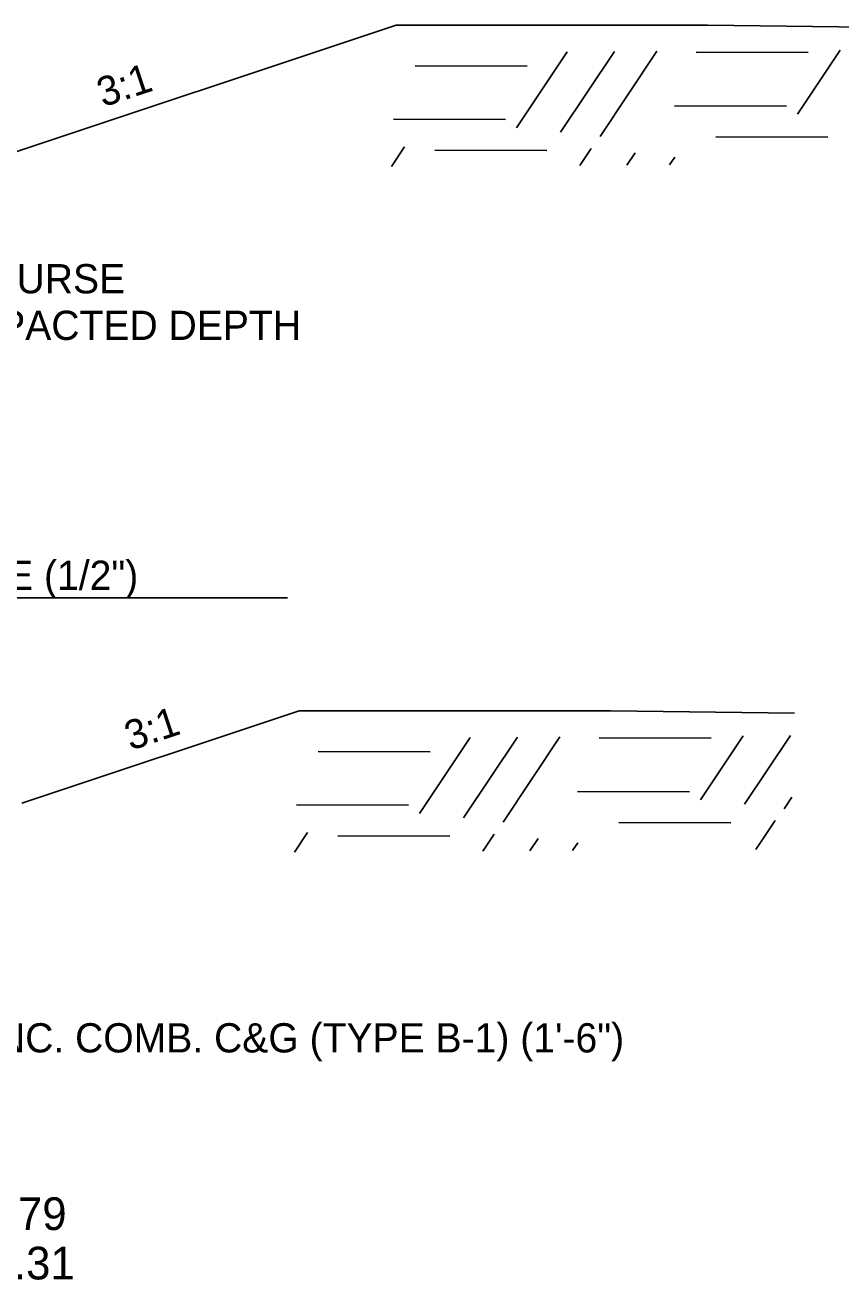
# Model space of a CAD drawing. Extents: x 1398183 to 1398373, y 1967240 to 1968889.
# Drawn here: x 1398289.03 to 1398305.5, y 1968479.92 to 1968505.23 of the extents above; entities that cross this region are included whole.
import ezdxf

# ---------------------------------------------------------------- set-up
doc = ezdxf.new("R2010")
doc.units = 0
for name, color, linetype in [('10', 7, 'Continuous'), ('19', 7, 'Continuous'), ('42', 7, 'Continuous'), ('9', 7, 'Continuous')]:
    doc.layers.add(name, color=color, linetype=linetype)

msp = doc.modelspace()

# ---------------------------------------------------------------- linework, layer by layer
at = {"layer": '19'}
for p, q in [((1398287.15, 1968502.113), (1398296.517, 1968505.235)), ((1398294.328, 1968493.678), (1398270.961, 1968493.678)), ((1398288.961, 1968489.534), (1398294.559, 1968491.4))]:
    msp.add_line(p, q, dxfattribs=at)
at = {"layer": '42'}
for points in [[(1398296.517, 1968505.235), (1398302.803, 1968505.235), (1398306.519, 1968505.184)], [(1398294.559, 1968491.4), (1398300.845, 1968491.4), (1398304.56, 1968491.349)]]:
    msp.add_lwpolyline(points, dxfattribs=at)
at = {"layer": '9'}
for p, q in [((1398299.971, 1968504.697), (1398298.949, 1968503.163)), ((1398300.924, 1968504.702), (1398299.839, 1968503.075)), ((1398301.784, 1968504.707), (1398300.637, 1968502.987)), ((1398304.836, 1968504.68), (1398302.574, 1968504.686)), ((1398305.482, 1968504.728), (1398304.621, 1968503.436)), ((1398299.164, 1968504.407), (1398296.902, 1968504.413)), ((1398304.397, 1968503.602), (1398302.135, 1968503.607)), ((1398298.725, 1968503.329), (1398296.463, 1968503.335)), ((1398296.689, 1968502.779), (1398296.425, 1968502.383)), ((1398305.235, 1968502.976), (1398302.973, 1968502.981)), ((1398299.563, 1968502.703), (1398297.301, 1968502.709)), ((1398300.453, 1968502.745), (1398300.226, 1968502.404)), ((1398301.343, 1968502.657), (1398301.178, 1968502.409)), ((1398302.141, 1968502.569), (1398302.038, 1968502.414)), ((1398298.013, 1968490.862), (1398296.991, 1968489.328)), ((1398298.966, 1968490.867), (1398297.881, 1968489.24)), ((1398299.826, 1968490.872), (1398298.679, 1968489.152)), ((1398303.524, 1968490.893), (1398302.662, 1968489.601)), ((1398304.476, 1968490.898), (1398303.553, 1968489.513)), ((1398302.878, 1968490.844), (1398300.616, 1968490.85)), ((1398297.206, 1968490.572), (1398294.944, 1968490.578)), ((1398302.439, 1968489.766), (1398300.177, 1968489.772)), ((1398304.504, 1968489.655), (1398304.351, 1968489.424)), ((1398296.767, 1968489.493), (1398294.505, 1968489.499)), ((1398303.277, 1968489.14), (1398301.015, 1968489.146)), ((1398304.167, 1968489.182), (1398303.778, 1968488.6)), ((1398294.731, 1968488.944), (1398294.467, 1968488.548)), ((1398297.605, 1968488.867), (1398295.343, 1968488.873)), ((1398298.495, 1968488.91), (1398298.268, 1968488.569)), ((1398299.385, 1968488.822), (1398299.22, 1968488.574)), ((1398300.183, 1968488.733), (1398300.08, 1968488.579))]:
    msp.add_line(p, q, dxfattribs=at)

# ---------------------------------------------------------------- texts
at = {"layer": '10'}
for p in [(1398290.602, 1968503.574), (1398291.159, 1968490.592)]:
    msp.add_text('3:1', height=0.59, rotation=18.4349, dxfattribs=at).set_placement(p)
msp.add_text('6\'-0" ACHM SURFACE COURSE (1/2")', height=0.59001, dxfattribs=at).set_placement((1398277.494, 1968493.839))
at = {"layer": '19'}
for s, p in [('AGGREGATE BASE COURSE', (1398280.132, 1968499.822)), ('(CLASS 7) - VAR. COMPACTED DEPTH', (1398280.132, 1968498.882))]:
    msp.add_text(s, height=0.59001, rotation=360, dxfattribs=at).set_placement(p)
for s, height, p in [('CONC. COMB. C&G (TYPE B-1) (1\'-6")', 0.59001, (1398287.276, 1968484.505)), ('STA. 338+85.00 TO STA. 340+53.79', 0.65999, (1398275.344, 1968480.922)), ('STA. 353+00.00 TO STA. 353+58.31', 0.65999, (1398275.508, 1968479.925))]:
    msp.add_text(s, height=height, dxfattribs=at).set_placement(p)

doc.saveas('drawing.dxf')
